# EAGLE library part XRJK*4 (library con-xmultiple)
RJ11 Connector without LED, 6 position, 4 contacts, thrue hole Source: XRJK-S-01-6-4-0-9M2(01).pdf
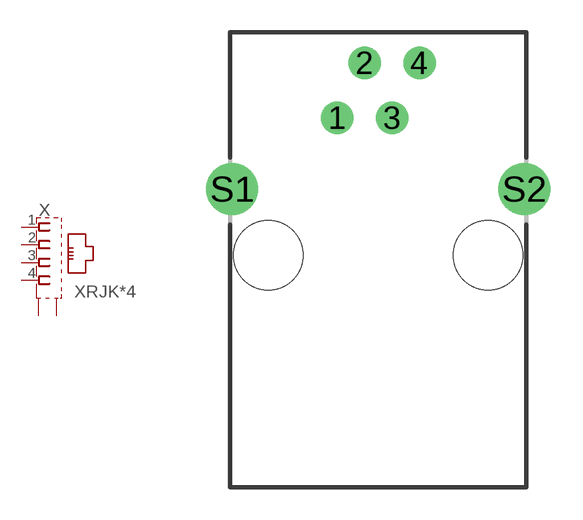
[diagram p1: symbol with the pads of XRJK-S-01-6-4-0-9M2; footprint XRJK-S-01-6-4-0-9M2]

Designator prefix X

## XRJK-S-01-6-4-0-9M2  [XRJK-S-01-6-4-0-9M2]
1  1  pas
2  2  pas
3  3  pas
4  4  pas
S1  S  pas
S2  S  pas

## Footprint XRJK-S-01-6-4-0-9M2 (pad centres in mm)
RJ11 Connector without LED, 6 position, 4 contacts, shielded, thrue hole Source: XRJK-S-01-6-4-0-9M2(01).pdf
drill 0.9 pad 1.5 round: 1 -1.905,6.35; 2 -0.635,8.89; 3 0.635,6.35; 4 1.905,8.89
drill 1.6 pad 2.184 round: S1 -6.75,3.05; S2 6.75,3.05
hole 3.2 at -5.08,0
hole 3.2 at 5.08,0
